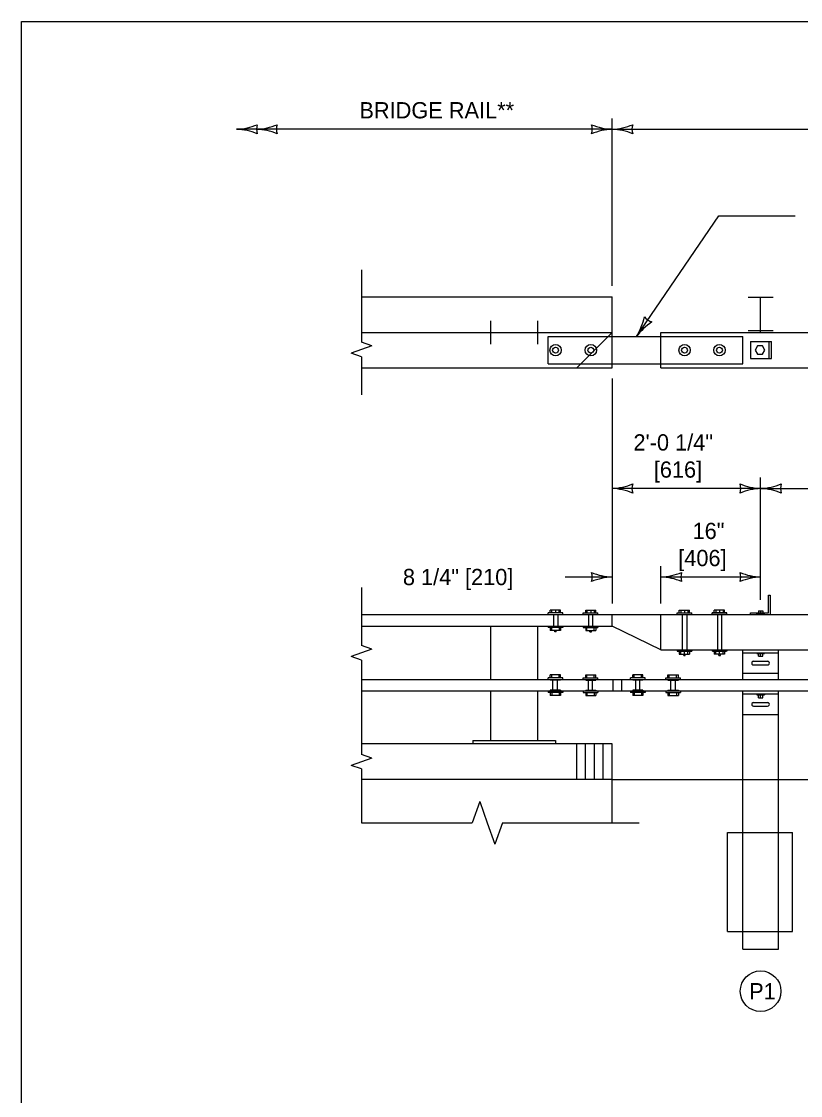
# Model space of a CAD drawing. Extents: x 49991.4 to 50021, y 49987.6 to 50011.4.
# Drawn here: x 49999.384 to 50002.258, y 49995.037 to 49998.999 of the extents above; entities that cross this region are included whole.
import ezdxf

# ---------------------------------------------------------------- set-up
doc = ezdxf.new("R2010")
doc.units = 0
for name, color, linetype in [('Level 1', 7, 'Continuous'), ('Level 2', 7, 'Continuous'), ('Level 3', 7, 'Continuous'), ('Level 4', 7, 'Continuous'), ('Level 6', 7, 'Continuous')]:
    doc.layers.add(name, color=color, linetype=linetype)

msp = doc.modelspace()

# ---------------------------------------------------------------- linework, layer by layer
at = {"layer": 'Level 1'}
for p, q in [((50000.6384, 49997.9834), (50001.5626, 49997.9834)), ((50001.5626, 49997.8514), (50001.5626, 49997.9834)), ((50002.0644, 49997.982), (50002.1568, 49997.982)), ((50002.1107, 49997.8514), (50002.1107, 49997.982)), ((50001.1152, 49997.8088), (50001.1152, 49997.8949)), ((50001.2891, 49997.8088), (50001.2891, 49997.8949)), ((50000.6384, 49997.8514), (50001.5626, 49997.8514)), ((50001.5626, 49997.7218), (50001.5626, 49997.8514)), ((50001.5626, 49997.8373), (50001.743, 49997.8373)), ((50001.743, 49997.7218), (50001.743, 49997.8514)), ((50001.743, 49997.8514), (50015.4519, 49997.8514)), ((50002.0644, 49997.8587), (50002.1568, 49997.8587)), ((50002.0738, 49997.8185), (50002.1508, 49997.8185)), ((50002.0739, 49997.7553), (50002.0739, 49997.8185)), ((50002.1424, 49997.7553), (50002.1424, 49997.8185)), ((50002.151, 49997.7553), (50002.151, 49997.8185)), ((50000.6384, 49997.7218), (50001.5626, 49997.7218)), ((50001.5626, 49997.736), (50001.743, 49997.736)), ((50001.743, 49997.7218), (50015.4519, 49997.7218)), ((50002.0738, 49997.7553), (50002.1508, 49997.7553)), ((50002.1393, 49996.8177), (50002.1393, 49996.8831)), ((50002.1393, 49996.8831), (50002.1452, 49996.8831)), ((50002.1452, 49996.8831), (50002.1452, 49996.8116)), ((50000.6384, 49996.8116), (50001.5626, 49996.8116)), ((50001.3806, 49996.8171), (50001.3266, 49996.8171)), ((50001.3266, 49996.8116), (50001.3266, 49996.8171)), ((50001.3719, 49996.8277), (50001.3336, 49996.8277)), ((50001.3336, 49996.8171), (50001.3336, 49996.8277)), ((50001.3399, 49996.8171), (50001.3399, 49996.8277)), ((50001.354, 49996.8277), (50001.354, 49996.8171)), ((50001.3673, 49996.8171), (50001.3673, 49996.8277)), ((50001.3719, 49996.8171), (50001.3719, 49996.8277)), ((50001.3806, 49996.8116), (50001.3806, 49996.8171)), ((50001.4561, 49996.8171), (50001.5103, 49996.8171)), ((50001.4561, 49996.8116), (50001.4561, 49996.8171)), ((50001.4651, 49996.8277), (50001.5032, 49996.8277)), ((50001.4651, 49996.8171), (50001.4651, 49996.8277)), ((50001.4694, 49996.8277), (50001.4694, 49996.8171)), ((50001.4841, 49996.8277), (50001.4841, 49996.8171)), ((50001.4969, 49996.8277), (50001.4969, 49996.8171)), ((50001.5032, 49996.8171), (50001.5032, 49996.8277)), ((50001.5103, 49996.8116), (50001.5103, 49996.8171)), ((50001.5626, 49996.7682), (50001.5626, 49996.8116)), ((50001.5626, 49996.8116), (50002.0298, 49996.8116)), ((50001.743, 49996.6812), (50001.743, 49996.8116)), ((50001.8024, 49996.8171), (50001.8566, 49996.8171)), ((50001.8024, 49996.8116), (50001.8024, 49996.8171)), ((50001.8104, 49996.8277), (50001.8485, 49996.8277)), ((50001.8104, 49996.8171), (50001.8104, 49996.8277)), ((50001.8166, 49996.8277), (50001.8166, 49996.8171)), ((50001.83, 49996.8277), (50001.83, 49996.8171)), ((50001.8424, 49996.8277), (50001.8424, 49996.8171)), ((50001.8485, 49996.8171), (50001.8485, 49996.8277)), ((50001.8566, 49996.8116), (50001.8566, 49996.8171)), ((50001.9321, 49996.8116), (50001.9321, 49996.8171)), ((50001.9862, 49996.8171), (50001.9321, 49996.8171)), ((50001.9347, 49996.8171), (50001.9836, 49996.8171)), ((50001.9774, 49996.8277), (50001.9391, 49996.8277)), ((50001.9391, 49996.8171), (50001.9391, 49996.8277)), ((50001.9454, 49996.8277), (50001.9454, 49996.8171)), ((50001.9587, 49996.8277), (50001.9587, 49996.8171)), ((50001.9729, 49996.8277), (50001.9729, 49996.8171)), ((50001.9774, 49996.8171), (50001.9774, 49996.8277)), ((50001.9862, 49996.8116), (50001.9862, 49996.8171)), ((50002.0298, 49996.8116), (50015.4519, 49996.8116)), ((50002.0737, 49996.8118), (50002.0737, 49996.8177)), ((50002.0737, 49996.8177), (50002.1393, 49996.8177)), ((50002.0963, 49996.8144), (50002.1248, 49996.8144)), ((50002.0963, 49996.8116), (50002.0963, 49996.8144)), ((50002.1025, 49996.825), (50002.1186, 49996.825)), ((50002.1025, 49996.825), (50002.1025, 49996.8144)), ((50002.1107, 49996.825), (50002.1107, 49996.8144)), ((50002.1186, 49996.825), (50002.1186, 49996.8144)), ((50002.1248, 49996.8116), (50002.1248, 49996.8144)), ((50000.6384, 49996.7682), (50001.5626, 49996.7682)), ((50001.1152, 49996.5719), (50001.1152, 49996.7682)), ((50001.2891, 49996.5719), (50001.2891, 49996.7682)), ((50001.3266, 49996.7682), (50001.3266, 49996.7629)), ((50001.3806, 49996.7682), (50001.3806, 49996.7629)), ((50001.4561, 49996.7682), (50001.4561, 49996.7629)), ((50001.5103, 49996.7682), (50001.5103, 49996.7629)), ((50001.743, 49996.6812), (50001.5626, 49996.7682)), ((50001.3806, 49996.7629), (50001.3266, 49996.7629)), ((50001.3336, 49996.7629), (50001.3336, 49996.7522)), ((50001.3719, 49996.7522), (50001.3336, 49996.7522)), ((50001.3399, 49996.7522), (50001.3399, 49996.7629)), ((50001.3514, 49996.7479), (50001.3514, 49996.7522)), ((50001.3567, 49996.7479), (50001.3514, 49996.7479)), ((50001.3567, 49996.7479), (50001.3567, 49996.7522)), ((50001.3673, 49996.7629), (50001.3673, 49996.7522)), ((50001.3719, 49996.7629), (50001.3719, 49996.7522)), ((50001.4561, 49996.7629), (50001.5103, 49996.7629)), ((50001.4651, 49996.7629), (50001.4651, 49996.7522)), ((50001.4651, 49996.7522), (50001.5032, 49996.7522)), ((50001.4694, 49996.7522), (50001.4694, 49996.7629)), ((50001.4802, 49996.7479), (50001.4802, 49996.7522)), ((50001.4802, 49996.7479), (50001.4865, 49996.7479)), ((50001.4865, 49996.7479), (50001.4865, 49996.7522)), ((50001.4969, 49996.7522), (50001.4969, 49996.7629)), ((50001.5032, 49996.7629), (50001.5032, 49996.7522)), ((50001.743, 49996.6812), (50002.0298, 49996.6812)), ((50001.8024, 49996.6812), (50001.8024, 49996.6759)), ((50001.8024, 49996.6759), (50001.8566, 49996.6759)), ((50001.8104, 49996.6759), (50001.8104, 49996.6652)), ((50001.8104, 49996.6652), (50001.8485, 49996.6652)), ((50001.8166, 49996.6652), (50001.8166, 49996.6759)), ((50001.8273, 49996.6607), (50001.8273, 49996.6652)), ((50001.8273, 49996.6607), (50001.8273, 49996.6652)), ((50001.8273, 49996.6607), (50001.8318, 49996.6607)), ((50001.83, 49996.6652), (50001.83, 49996.6759)), ((50001.8318, 49996.6607), (50001.8318, 49996.6652)), ((50001.8424, 49996.6652), (50001.8424, 49996.6759)), ((50001.8485, 49996.6759), (50001.8485, 49996.6652)), ((50001.8566, 49996.6812), (50001.8566, 49996.6759)), ((50001.9321, 49996.6812), (50001.9321, 49996.6759)), ((50001.9862, 49996.6759), (50001.9321, 49996.6759)), ((50001.9347, 49996.6759), (50001.9836, 49996.6759)), ((50001.9391, 49996.6759), (50001.9391, 49996.6652)), ((50001.9774, 49996.6652), (50001.9391, 49996.6652)), ((50001.9454, 49996.6652), (50001.9454, 49996.6759)), ((50001.956, 49996.6607), (50001.956, 49996.6652)), ((50001.956, 49996.6607), (50001.9623, 49996.6607)), ((50001.9587, 49996.6652), (50001.9587, 49996.6759)), ((50001.9623, 49996.6607), (50001.9623, 49996.6652)), ((50001.9729, 49996.6652), (50001.9729, 49996.6759)), ((50001.9774, 49996.6759), (50001.9774, 49996.6652)), ((50001.9862, 49996.6812), (50001.9862, 49996.6759)), ((50002.0298, 49996.6812), (50015.4519, 49996.6812)), ((50002.0449, 49996.5719), (50002.0449, 49996.6812)), ((50002.0449, 49996.6705), (50002.1762, 49996.6705)), ((50002.0963, 49996.6705), (50002.0963, 49996.6679)), ((50002.0963, 49996.6679), (50002.1248, 49996.6679)), ((50002.1025, 49996.6572), (50002.1025, 49996.6679)), ((50002.1025, 49996.6572), (50002.1186, 49996.6572)), ((50002.1107, 49996.6572), (50002.1107, 49996.6679)), ((50002.1186, 49996.6572), (50002.1186, 49996.6679)), ((50002.1248, 49996.6705), (50002.1248, 49996.6679)), ((50002.1762, 49996.5719), (50002.1762, 49996.6812)), ((50002.0839, 49996.6389), (50002.1372, 49996.6389)), ((50002.0849, 49996.6253), (50002.1355, 49996.6253)), ((50000.6384, 49996.5719), (50002.0449, 49996.5719)), ((50001.3806, 49996.5783), (50001.3266, 49996.5783)), ((50001.3266, 49996.5719), (50001.3266, 49996.5783)), ((50001.3719, 49996.5888), (50001.3336, 49996.5888)), ((50001.3336, 49996.5783), (50001.3336, 49996.5888)), ((50001.3399, 49996.5783), (50001.3399, 49996.5888)), ((50001.3673, 49996.5783), (50001.3673, 49996.5888)), ((50001.3719, 49996.5783), (50001.3719, 49996.5888)), ((50001.3806, 49996.5719), (50001.3806, 49996.5783)), ((50001.4561, 49996.5783), (50001.5103, 49996.5783)), ((50001.4561, 49996.5719), (50001.4561, 49996.5783)), ((50001.4651, 49996.5888), (50001.5032, 49996.5888)), ((50001.4651, 49996.5783), (50001.4651, 49996.5888)), ((50001.4694, 49996.5783), (50001.4694, 49996.5888)), ((50001.4969, 49996.5783), (50001.4969, 49996.5888)), ((50001.5032, 49996.5783), (50001.5032, 49996.5888)), ((50001.5103, 49996.5719), (50001.5103, 49996.5783)), ((50001.5653, 49996.5719), (50001.5653, 49996.5294)), ((50001.5972, 49996.5719), (50001.5972, 49996.5294)), ((50001.6844, 49996.5783), (50001.6302, 49996.5783)), ((50001.6302, 49996.5719), (50001.6302, 49996.5783)), ((50001.6755, 49996.5888), (50001.639, 49996.5888)), ((50001.639, 49996.5783), (50001.639, 49996.5888)), ((50001.6435, 49996.5783), (50001.6435, 49996.5888)), ((50001.671, 49996.5783), (50001.671, 49996.5888)), ((50001.6755, 49996.5783), (50001.6755, 49996.5888)), ((50001.6844, 49996.5719), (50001.6844, 49996.5783)), ((50001.7607, 49996.5783), (50001.8149, 49996.5783)), ((50001.7607, 49996.5719), (50001.7607, 49996.5783)), ((50001.7686, 49996.5783), (50001.7686, 49996.5888)), ((50001.7686, 49996.5888), (50001.807, 49996.5888)), ((50001.7732, 49996.5783), (50001.7732, 49996.5888)), ((50001.8007, 49996.5783), (50001.8007, 49996.5888)), ((50001.807, 49996.5783), (50001.807, 49996.5888)), ((50001.8149, 49996.5719), (50001.8149, 49996.5783)), ((50002.0449, 49996.595), (50002.1762, 49996.595)), ((50002.0449, 49996.5719), (50012.5032, 49996.5719)), ((50000.6384, 49996.5294), (50002.0449, 49996.5294)), ((50001.1152, 49996.3464), (50001.1152, 49996.5294)), ((50001.2891, 49996.3464), (50001.2891, 49996.5294)), ((50001.3266, 49996.5294), (50001.3266, 49996.5231)), ((50001.3806, 49996.5294), (50001.3806, 49996.5231)), ((50001.4561, 49996.5294), (50001.4561, 49996.5231)), ((50001.5103, 49996.5294), (50001.5103, 49996.5231)), ((50001.6302, 49996.5294), (50001.6302, 49996.5231)), ((50001.6844, 49996.5294), (50001.6844, 49996.5231)), ((50001.7607, 49996.5294), (50001.7607, 49996.5231)), ((50001.8149, 49996.5294), (50001.8149, 49996.5231)), ((50002.0449, 49996.5294), (50007.0485, 49996.5294)), ((50002.0449, 49996.2026), (50002.0449, 49996.5294)), ((50002.1762, 49996.2026), (50002.1762, 49996.5294)), ((50001.3806, 49996.5231), (50001.3266, 49996.5231)), ((50001.3336, 49996.5231), (50001.3336, 49996.5124)), ((50001.3719, 49996.5124), (50001.3336, 49996.5124)), ((50001.3399, 49996.5231), (50001.3399, 49996.5124)), ((50001.3673, 49996.5231), (50001.3673, 49996.5124)), ((50001.3719, 49996.5231), (50001.3719, 49996.5124)), ((50001.4561, 49996.5231), (50001.5103, 49996.5231)), ((50001.4651, 49996.5231), (50001.4651, 49996.5124)), ((50001.4651, 49996.5124), (50001.5032, 49996.5124)), ((50001.4694, 49996.5231), (50001.4694, 49996.5124)), ((50001.4969, 49996.5231), (50001.4969, 49996.5124)), ((50001.5032, 49996.5231), (50001.5032, 49996.5124)), ((50001.6844, 49996.5231), (50001.6302, 49996.5231)), ((50001.639, 49996.5231), (50001.639, 49996.5124)), ((50001.6755, 49996.5124), (50001.639, 49996.5124)), ((50001.6435, 49996.5231), (50001.6435, 49996.5124)), ((50001.671, 49996.5231), (50001.671, 49996.5124)), ((50001.6755, 49996.5231), (50001.6755, 49996.5124)), ((50001.7607, 49996.5231), (50001.8149, 49996.5231)), ((50001.7686, 49996.5231), (50001.7686, 49996.5124)), ((50001.7686, 49996.5124), (50001.807, 49996.5124)), ((50001.7732, 49996.5231), (50001.7732, 49996.5124)), ((50001.8007, 49996.5231), (50001.8007, 49996.5124)), ((50001.807, 49996.5231), (50001.807, 49996.5124)), ((50002.0449, 49996.5187), (50002.1762, 49996.5187)), ((50002.0963, 49996.5187), (50002.0963, 49996.5152)), ((50002.0963, 49996.5152), (50002.1248, 49996.5152)), ((50002.1025, 49996.5044), (50002.1025, 49996.5152)), ((50002.1025, 49996.5044), (50002.1186, 49996.5044)), ((50002.1107, 49996.5044), (50002.1107, 49996.5152)), ((50002.1186, 49996.5044), (50002.1186, 49996.5152)), ((50002.1248, 49996.5187), (50002.1248, 49996.5152)), ((50002.0839, 49996.4868), (50002.1372, 49996.4868)), ((50002.0849, 49996.4732), (50002.1355, 49996.4732)), ((50002.0449, 49996.4422), (50002.1762, 49996.4422)), ((50001.5626, 49996.334), (50000.6384, 49996.334)), ((50001.0486, 49996.3464), (50001.3532, 49996.3464)), ((50001.0486, 49996.3464), (50001.0486, 49996.334)), ((50001.3532, 49996.3464), (50001.3532, 49996.334)), ((50001.4321, 49996.2026), (50001.4321, 49996.334)), ((50001.4647, 49996.2026), (50001.4647, 49996.334)), ((50001.4974, 49996.2026), (50001.4974, 49996.334)), ((50001.53, 49996.2026), (50001.53, 49996.334)), ((50001.5626, 49996.2026), (50001.5626, 49996.334)), ((50001.5626, 49996.2026), (50000.6384, 49996.2026)), ((50001.5626, 49996.2026), (50015.4519, 49996.2026))]:
    msp.add_line(p, q, dxfattribs=at)
for points in [[(49999.3835, 49998.9992), (50016.7501, 49998.9992), (50016.7501, 49987.7988), (49999.3835, 49987.7988)], [(50002.099, 49997.7721), (50002.1179, 49997.7721), (50002.1261, 49997.7871), (50002.1179, 49997.8021), (50002.099, 49997.8021), (50002.0908, 49997.7871)]]:
    msp.add_lwpolyline(points, close=True, dxfattribs=at)
for centre, radius in [((50001.354, 49997.7866), 0.0209), ((50001.354, 49997.7866), 0.0109), ((50001.4841, 49997.7866), 0.0209), ((50001.4842, 49997.7866), 0.0109), ((50001.83, 49997.7866), 0.0209), ((50001.83, 49997.7866), 0.0109), ((50001.9587, 49997.7866), 0.0209), ((50001.9587, 49997.7866), 0.0109)]:
    msp.add_circle(centre, radius, dxfattribs=at)
for centre, start, end in [((50002.0844, 49996.6321), 86.0196, 273.9804), ((50002.136, 49996.6321), 266.0196, 93.9804), ((50002.0844, 49996.48), 86.0196, 273.9804), ((50002.136, 49996.48), 266.0196, 93.9804)]:
    msp.add_arc(centre, 0.00681, start, end, dxfattribs=at)
at = {"layer": 'Level 2'}
msp.add_circle((50002.1106, 49995.4216), 0.075, dxfattribs=at)
at = {"layer": 'Level 3'}
for p, q in [((50001.5626, 49998.0234), (50001.5626, 49998.6417)), ((50001.5626, 49998.6017), (50000.1774, 49998.6017)), ((50001.5626, 49998.6017), (50014.9504, 49998.6017)), ((50001.6528, 49997.8373), (50001.9564, 49998.2816)), ((50001.9564, 49998.2816), (50002.2382, 49998.2816)), ((50001.5626, 49997.6818), (50001.5626, 49996.8516)), ((50002.1107, 49996.865), (50002.1107, 49997.3163)), ((50002.1107, 49997.2763), (50001.5626, 49997.2763)), ((50002.1107, 49997.2763), (50006.2831, 49997.2763)), ((50001.743, 49996.8516), (50001.743, 49996.9898)), ((50001.3892, 49996.9498), (50001.5626, 49996.9498)), ((50001.743, 49996.9498), (50002.1107, 49996.9498))]:
    msp.add_line(p, q, dxfattribs=at)
for centre, radius, start, end in [((50000.1659, 49998.8344), 0.233, 272.8273, 292.0772), ((50000.1682, 49998.3795), 0.2223, 67.456, 87.6395), ((50000.2393, 49998.8344), 0.233, 272.8273, 292.0772), ((50000.3056, 49998.6017), 0.0548, 162.1388, 197.8612), ((50000.2417, 49998.3795), 0.2223, 67.456, 87.6395), ((50000.379, 49998.6017), 0.0548, 162.1388, 197.8612), ((50001.5718, 49998.8238), 0.2223, 247.456, 267.6395), ((50001.4344, 49998.6017), 0.0548, 342.1388, 17.8612), ((50001.5741, 49998.3689), 0.233, 92.8273, 112.0772), ((50001.5511, 49998.8344), 0.233, 272.8273, 292.0772), ((50001.5534, 49998.3795), 0.2223, 67.456, 87.6395), ((50001.6908, 49998.6017), 0.0548, 162.1388, 197.8612), ((50001.4542, 49997.9591), 0.233, 328.4879, 347.7377), ((50001.8311, 49997.7044), 0.2223, 123.1166, 143.3001), ((50001.7251, 49997.9432), 0.0548, 217.7994, 253.5217), ((50001.5511, 49997.509), 0.233, 272.8273, 292.0772), ((50001.6908, 49997.2763), 0.0548, 162.1388, 197.8612), ((50002.1199, 49997.4984), 0.2223, 247.456, 267.6395), ((50001.9825, 49997.2763), 0.0548, 342.1388, 17.8612), ((50002.0992, 49997.509), 0.233, 272.8273, 292.0772), ((50002.2389, 49997.2763), 0.0548, 162.1388, 197.8612), ((50001.5534, 49997.0542), 0.2223, 67.456, 87.6395), ((50002.1222, 49997.0436), 0.233, 92.8273, 112.0772), ((50002.1015, 49997.0542), 0.2223, 67.456, 87.6395), ((50001.5718, 49997.1719), 0.2223, 247.456, 267.6395), ((50001.4344, 49996.9498), 0.0548, 342.1388, 17.8612), ((50001.7315, 49997.1825), 0.233, 272.8273, 292.0772), ((50001.8712, 49996.9498), 0.0548, 162.1388, 197.8612), ((50002.1199, 49997.1719), 0.2223, 247.456, 267.6395), ((50001.9825, 49996.9498), 0.0548, 342.1388, 17.8612), ((50001.5741, 49996.7171), 0.233, 92.8273, 112.0772), ((50001.7338, 49996.7277), 0.2223, 67.456, 87.6395), ((50002.1222, 49996.7171), 0.233, 92.8273, 112.0772)]:
    msp.add_arc(centre, radius, start, end, dxfattribs=at)
at = {"layer": 'Level 4'}
for p, q in [((50001.3266, 49997.736), (50001.3266, 49997.8373)), ((50001.3266, 49997.8373), (50001.5626, 49997.8373)), ((50001.4322, 49997.7218), (50001.5626, 49997.8514)), ((50001.743, 49997.8373), (50002.0449, 49997.8373)), ((50002.0449, 49997.736), (50002.0449, 49997.8373)), ((50001.3266, 49997.736), (50001.5626, 49997.736)), ((50001.743, 49997.736), (50002.0449, 49997.736)), ((50001.347, 49996.8116), (50001.347, 49996.7682)), ((50001.3621, 49996.8116), (50001.3621, 49996.7682)), ((50001.4756, 49996.8116), (50001.4756, 49996.7682)), ((50001.4907, 49996.8116), (50001.4907, 49996.7682)), ((50001.821, 49996.8116), (50001.821, 49996.6812)), ((50001.838, 49996.8116), (50001.838, 49996.6812)), ((50001.9517, 49996.8116), (50001.9517, 49996.6812)), ((50001.9668, 49996.8116), (50001.9668, 49996.6812)), ((50001.3336, 49996.5693), (50001.3336, 49996.5719)), ((50001.3719, 49996.5693), (50001.3336, 49996.5693)), ((50001.3399, 49996.5693), (50001.3399, 49996.5719)), ((50001.3443, 49996.532), (50001.3443, 49996.5693)), ((50001.3611, 49996.532), (50001.3611, 49996.5693)), ((50001.3673, 49996.5693), (50001.3673, 49996.5719)), ((50001.3719, 49996.5693), (50001.3719, 49996.5719)), ((50001.4651, 49996.5693), (50001.4651, 49996.5719)), ((50001.4651, 49996.5693), (50001.5032, 49996.5693)), ((50001.4694, 49996.5693), (50001.4694, 49996.5719)), ((50001.4756, 49996.532), (50001.4756, 49996.5693)), ((50001.4907, 49996.532), (50001.4907, 49996.5693)), ((50001.4969, 49996.5693), (50001.4969, 49996.5719)), ((50001.5032, 49996.5693), (50001.5032, 49996.5719)), ((50001.639, 49996.5693), (50001.639, 49996.5719)), ((50001.6755, 49996.5693), (50001.639, 49996.5693)), ((50001.6435, 49996.5693), (50001.6435, 49996.5719)), ((50001.6498, 49996.532), (50001.6498, 49996.5693)), ((50001.6649, 49996.532), (50001.6649, 49996.5693)), ((50001.671, 49996.5693), (50001.671, 49996.5719)), ((50001.6755, 49996.5693), (50001.6755, 49996.5719)), ((50001.7686, 49996.5693), (50001.7686, 49996.5719)), ((50001.7686, 49996.5693), (50001.807, 49996.5693)), ((50001.7732, 49996.5693), (50001.7732, 49996.5719)), ((50001.7793, 49996.532), (50001.7793, 49996.5693)), ((50001.7962, 49996.532), (50001.7962, 49996.5693)), ((50001.8007, 49996.5693), (50001.8007, 49996.5719)), ((50001.807, 49996.5693), (50001.807, 49996.5719)), ((50001.3719, 49996.532), (50001.3336, 49996.532)), ((50001.3336, 49996.532), (50001.3336, 49996.5294)), ((50001.3399, 49996.532), (50001.3399, 49996.5294)), ((50001.3673, 49996.532), (50001.3673, 49996.5294)), ((50001.3719, 49996.532), (50001.3719, 49996.5294)), ((50001.4651, 49996.532), (50001.5032, 49996.532)), ((50001.4651, 49996.532), (50001.4651, 49996.5294)), ((50001.4694, 49996.532), (50001.4694, 49996.5294)), ((50001.4969, 49996.532), (50001.4969, 49996.5294)), ((50001.5032, 49996.532), (50001.5032, 49996.5294)), ((50001.6755, 49996.532), (50001.639, 49996.532)), ((50001.639, 49996.532), (50001.639, 49996.5294)), ((50001.6435, 49996.532), (50001.6435, 49996.5294)), ((50001.671, 49996.532), (50001.671, 49996.5294)), ((50001.6755, 49996.532), (50001.6755, 49996.5294)), ((50001.7686, 49996.532), (50001.807, 49996.532)), ((50001.7686, 49996.532), (50001.7686, 49996.5294)), ((50001.7732, 49996.532), (50001.7732, 49996.5294)), ((50001.8007, 49996.532), (50001.8007, 49996.5294)), ((50001.807, 49996.532), (50001.807, 49996.5294)), ((50001.5626, 49996.0427), (50001.5626, 49996.2026)), ((50002.0449, 49995.5766), (50002.0449, 49996.2026)), ((50002.1762, 49995.5766), (50002.1762, 49996.2026)), ((50001.988, 49996.0072), (50002.2278, 49996.0072)), ((50001.988, 49995.6414), (50001.988, 49996.0072)), ((50002.2278, 49995.6414), (50002.2278, 49996.0072)), ((50001.988, 49995.6414), (50002.2278, 49995.6414)), ((50002.0449, 49995.5766), (50002.1762, 49995.5766))]:
    msp.add_line(p, q, dxfattribs=at)
at = {"layer": 'Level 6'}
for p, q in [((50000.6384, 49998.0834), (50000.6384, 49997.8158)), ((50000.6763, 49997.8025), (50000.6384, 49997.8158)), ((50000.6763, 49997.8025), (50000.6384, 49997.789)), ((50000.6384, 49997.789), (50000.6005, 49997.7755)), ((50000.6384, 49997.7622), (50000.6005, 49997.7755)), ((50000.6384, 49997.7622), (50000.6384, 49997.6218)), ((50000.6384, 49996.9116), (50000.6384, 49996.6969)), ((50000.6763, 49996.6836), (50000.6384, 49996.6969)), ((50000.6384, 49996.6701), (50000.6005, 49996.6566)), ((50000.6384, 49996.6433), (50000.6005, 49996.6566)), ((50000.6763, 49996.6836), (50000.6384, 49996.6701)), ((50000.6384, 49996.6433), (50000.6384, 49996.2951)), ((50000.6763, 49996.2818), (50000.6384, 49996.2951)), ((50000.6384, 49996.2683), (50000.6005, 49996.2548)), ((50000.6384, 49996.2415), (50000.6005, 49996.2548)), ((50000.6763, 49996.2818), (50000.6384, 49996.2683)), ((50000.6384, 49996.2415), (50000.6384, 49996.0427)), ((50001.0744, 49996.1218), (50001.0465, 49996.0427)), ((50001.0744, 49996.1218), (50001.1022, 49996.0427)), ((50000.6384, 49996.0427), (50001.0465, 49996.0427)), ((50001.1022, 49996.0427), (50001.1305, 49995.9637)), ((50001.1584, 49996.0427), (50001.1305, 49995.9637)), ((50001.1584, 49996.0427), (50001.6626, 49996.0427))]:
    msp.add_line(p, q, dxfattribs=at)

# ---------------------------------------------------------------- texts
at = {"layer": 'Level 2'}
for s, p in [('BRIDGE RAIL**', (50000.6303, 49998.6417)), ('2\'-0 1/4"', (50001.6414, 49997.4163)), ('[616]', (50001.7164, 49997.3163)), ('16"', (50001.8595, 49997.0898)), ('[406]', (50001.8066, 49996.9898)), ('8 1/4" [210]', (50000.7907, 49996.9198)), ('P1', (50002.0683, 49995.3917))]:
    msp.add_text(s, height=0.06, dxfattribs=at).set_placement(p)

doc.saveas('drawing.dxf')
